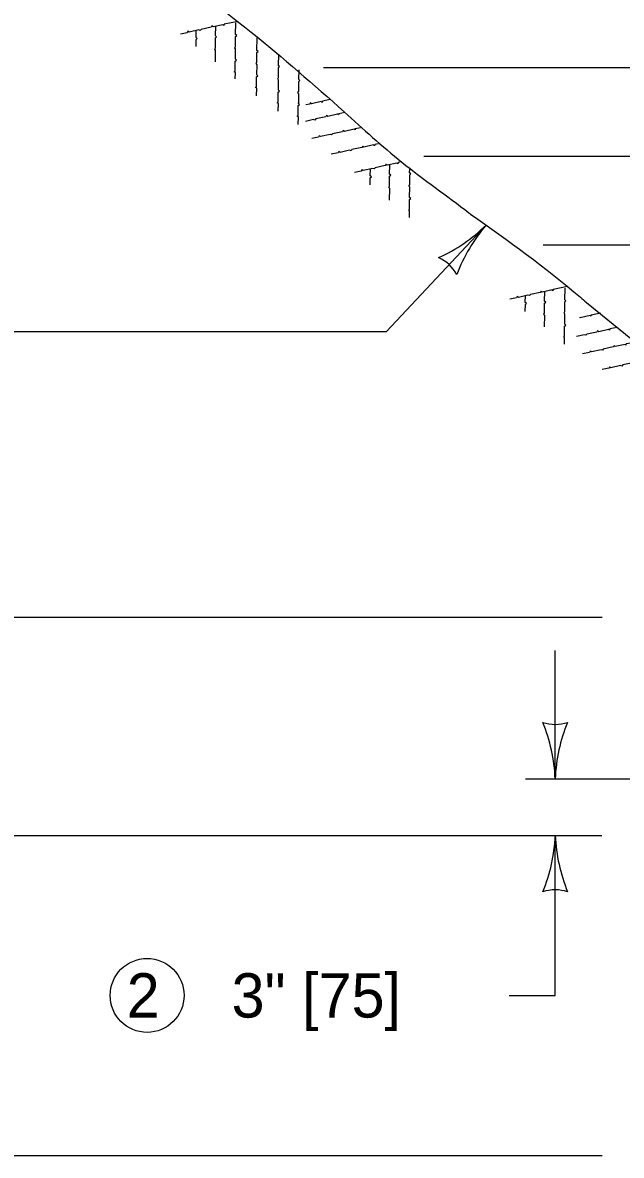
# Model space of a CAD drawing. Extents: x 49991.4 to 50021, y 49987.6 to 50011.4.
# Drawn here: x 50001.509 to 50002.319, y 49989.325 to 49990.858 of the extents above; entities that cross this region are included whole.
import ezdxf

# ---------------------------------------------------------------- set-up
doc = ezdxf.new("R2010")
doc.units = 0
for name, color, linetype in [('Level 1', 7, 'Continuous'), ('Level 2', 7, 'Continuous'), ('Level 3', 7, 'Continuous')]:
    doc.layers.add(name, color=color, linetype=linetype)

msp = doc.modelspace()

# ---------------------------------------------------------------- linework, layer by layer
at = {"layer": 'Level 1'}
for p, q in [((50001.9159, 49990.7972), (50003.1609, 49990.7972)), ((50002.0519, 49990.6772), (50003.0002, 49990.6772)), ((50002.2134, 49990.5572), (50002.9008, 49990.5572)), ((50002.2719, 49990.4789), (50002.3943, 49990.3794))]:
    msp.add_line(p, q, dxfattribs=at)
for points in [[(50001.8007, 49990.8593), (50001.7815, 49990.8556), (50001.781, 49990.8538), (50001.7798, 49990.8549), (50001.7666, 49990.8519), (50001.765, 49990.8532), (50001.7639, 49990.8515), (50001.7505, 49990.8486), (50001.7492, 49990.8471), (50001.7473, 49990.8478), (50001.7343, 49990.8448), (50001.7326, 49990.846), (50001.7316, 49990.8441), (50001.7225, 49990.8423)], [(50001.7697, 49990.8048), (50001.77, 49990.8204), (50001.7688, 49990.822), (50001.7698, 49990.8236), (50001.7698, 49990.8371), (50001.7713, 49990.8384), (50001.7697, 49990.8397), (50001.7702, 49990.8528)], [(50001.7965, 49990.7815), (50001.7969, 49990.7905), (50001.7953, 49990.7912), (50001.7966, 49990.7922), (50001.7967, 49990.8057), (50001.7984, 49990.807), (50001.797, 49990.8084), (50001.7972, 49990.8222), (50001.796, 49990.8238), (50001.7971, 49990.8255), (50001.7971, 49990.8388), (50001.7986, 49990.8402), (50001.7971, 49990.8415), (50001.7975, 49990.8573)], [(50001.7436, 49990.8255), (50001.7437, 49990.835), (50001.7452, 49990.8364), (50001.7436, 49990.8377), (50001.7439, 49990.8472)], [(50001.8254, 49990.7587), (50001.8257, 49990.769), (50001.8241, 49990.7698), (50001.8255, 49990.7708), (50001.8255, 49990.7842), (50001.8272, 49990.7856), (50001.8258, 49990.787), (50001.8261, 49990.8008), (50001.8249, 49990.8024), (50001.8259, 49990.804), (50001.826, 49990.8175), (50001.8275, 49990.8188), (50001.826, 49990.8202), (50001.8264, 49990.8374)], [(50001.8547, 49990.7381), (50001.855, 49990.7485), (50001.8534, 49990.7492), (50001.8547, 49990.7502), (50001.8548, 49990.7637), (50001.8565, 49990.765), (50001.8551, 49990.7664), (50001.8553, 49990.7801), (50001.8541, 49990.7818), (50001.8552, 49990.7835), (50001.8552, 49990.7968), (50001.8567, 49990.7982), (50001.8552, 49990.7995), (50001.8556, 49990.8149)], [(50001.8825, 49990.7487), (50001.8827, 49990.7615), (50001.8815, 49990.7631), (50001.8826, 49990.7648), (50001.8826, 49990.7781), (50001.8841, 49990.7795), (50001.8825, 49990.7809), (50001.883, 49990.7938)], [(50001.8818, 49990.7201), (50001.8822, 49990.7303), (50001.8805, 49990.7311), (50001.8817, 49990.732), (50001.8819, 49990.7455), (50001.8837, 49990.7468), (50001.8821, 49990.7483), (50001.8822, 49990.7491)], [(50001.8992, 49990.7486), (50001.8983, 49990.7493), (50001.8973, 49990.7476), (50001.8923, 49990.7464)], [(50001.925, 49990.7536), (50001.9147, 49990.7516), (50001.9144, 49990.7499), (50001.913, 49990.7509), (50001.8999, 49990.7479), (50001.8991, 49990.7487)], [(50001.9447, 49990.7361), (50001.9367, 49990.7345), (50001.9363, 49990.7328), (50001.9351, 49990.7338), (50001.9219, 49990.7308), (50001.9202, 49990.7323), (50001.9192, 49990.7304), (50001.9058, 49990.7277), (50001.9044, 49990.726), (50001.9026, 49990.7267), (50001.8918, 49990.7242)], [(50001.9662, 49990.7156), (50001.959, 49990.7142), (50001.9587, 49990.7125), (50001.9574, 49990.7135), (50001.9443, 49990.7106), (50001.9426, 49990.712), (50001.9416, 49990.7102), (50001.9281, 49990.7074), (50001.9268, 49990.7058), (50001.9249, 49990.7065), (50001.9118, 49990.7035), (50001.9102, 49990.7046), (50001.9092, 49990.7029), (50001.9001, 49990.701)], [(50001.9929, 49990.6943), (50001.9855, 49990.6929), (50001.9851, 49990.6911), (50001.9839, 49990.6922), (50001.9708, 49990.6893), (50001.9691, 49990.6906), (50001.968, 49990.6889), (50001.9545, 49990.686), (50001.9533, 49990.6845), (50001.9514, 49990.6851), (50001.9384, 49990.6821), (50001.9367, 49990.6833), (50001.9357, 49990.6814), (50001.9266, 49990.6796)], [(50002.0215, 49990.6693), (50002.0171, 49990.6684), (50002.0166, 49990.6666), (50002.0154, 49990.6677), (50002.0023, 49990.6648), (50002.0006, 49990.6661), (50001.9995, 49990.6644), (50001.986, 49990.6615), (50001.9848, 49990.66), (50001.9829, 49990.6606), (50001.9699, 49990.6576), (50001.9682, 49990.6589), (50001.9672, 49990.657), (50001.9581, 49990.6551)], [(50001.9793, 49990.6383), (50001.9793, 49990.6479), (50001.9808, 49990.6493), (50001.9793, 49990.6506), (50001.9795, 49990.6601)], [(50002.0053, 49990.6176), (50002.0056, 49990.6333), (50002.0044, 49990.6348), (50002.0054, 49990.6365), (50002.0055, 49990.65), (50002.007, 49990.6513), (50002.0054, 49990.6526), (50002.0058, 49990.665)], [(50002.0322, 49990.5943), (50002.0325, 49990.6033), (50002.031, 49990.6041), (50002.0322, 49990.605), (50002.0324, 49990.6186), (50002.0341, 49990.6199), (50002.0326, 49990.6213), (50002.0328, 49990.635), (50002.0316, 49990.6366), (50002.0327, 49990.6383), (50002.0327, 49990.6517), (50002.0342, 49990.6531), (50002.0326, 49990.6545), (50002.0328, 49990.6597)], [(50002.2461, 49990.5006), (50002.2269, 49990.4969), (50002.2264, 49990.4951), (50002.2252, 49990.4962), (50002.212, 49990.4932), (50002.2104, 49990.4945), (50002.2093, 49990.4928), (50002.1959, 49990.4899), (50002.1946, 49990.4884), (50002.1926, 49990.4891), (50002.1797, 49990.4861), (50002.178, 49990.4873), (50002.177, 49990.4854), (50002.1679, 49990.4836)], [(50002.2419, 49990.4228), (50002.2423, 49990.4318), (50002.2407, 49990.4325), (50002.242, 49990.4335), (50002.2421, 49990.447), (50002.2438, 49990.4483), (50002.2424, 49990.4497), (50002.2426, 49990.4635), (50002.2414, 49990.4651), (50002.2425, 49990.4668), (50002.2425, 49990.4801), (50002.244, 49990.4815), (50002.2425, 49990.4828), (50002.2429, 49990.4986)], [(50002.189, 49990.4668), (50002.1891, 49990.4763), (50002.1906, 49990.4777), (50002.189, 49990.479), (50002.1893, 49990.4885)], [(50002.2151, 49990.4461), (50002.2154, 49990.4617), (50002.2142, 49990.4633), (50002.2152, 49990.4649), (50002.2152, 49990.4784), (50002.2167, 49990.4797), (50002.2151, 49990.4811), (50002.2156, 49990.4941)], [(50002.2906, 49990.4647), (50002.2782, 49990.4622), (50002.2779, 49990.4605), (50002.2766, 49990.4615), (50002.2634, 49990.4585), (50002.2626, 49990.4593)], [(50002.3133, 49990.4452), (50002.3033, 49990.4433), (50002.3029, 49990.4415), (50002.3016, 49990.4425), (50002.2884, 49990.4396), (50002.2869, 49990.441), (50002.2857, 49990.4392), (50002.2723, 49990.4364), (50002.271, 49990.4348), (50002.2691, 49990.4355), (50002.2583, 49990.433)], [(50002.3379, 49990.4252), (50002.3256, 49990.423), (50002.3252, 49990.4212), (50002.324, 49990.4222), (50002.3108, 49990.4194), (50002.3091, 49990.4207), (50002.3081, 49990.419), (50002.2946, 49990.4162), (50002.2933, 49990.4145), (50002.2915, 49990.4152), (50002.2784, 49990.4122), (50002.2767, 49990.4134), (50002.2758, 49990.4116), (50002.2666, 49990.4098)], [(50002.3639, 49990.404), (50002.3521, 49990.4016), (50002.3517, 49990.3999), (50002.3505, 49990.4009), (50002.3373, 49990.398), (50002.3356, 49990.3993), (50002.3346, 49990.3976), (50002.3211, 49990.3948), (50002.3198, 49990.3932), (50002.3179, 49990.3938), (50002.3049, 49990.3909), (50002.3033, 49990.3919), (50002.3022, 49990.3902), (50002.2931, 49990.3884)]]:
    msp.add_lwpolyline(points, dxfattribs=at)
for points in [[(50001.6697, 49990.9573), (50001.8181, 49990.8449), (50001.944, 49990.737), (50002.0219, 49990.669), (50002.1128, 49990.6004), (50002.1151, 49990.5986)], [(50002.1151, 49990.5986), (50002.2635, 49990.4862), (50002.2719, 49990.4789)]]:
    msp.add_spline(points, degree=3, dxfattribs=at)
at = {"layer": 'Level 2'}
msp.add_circle((50001.6774, 49989.5417), 0.05, dxfattribs=at)
at = {"layer": 'Level 3'}
for p, q in [((50002.1361, 49990.5839), (50002.0012, 49990.44)), ((50001.0483, 49990.44), (50002.0012, 49990.44)), ((50001.4254, 49990.0533), (50002.2929, 49990.0533)), ((50002.2295, 49989.8349), (50002.2295, 49990.0083)), ((50002.1895, 49989.8349), (50003.255, 49989.8349)), ((50001.4254, 49989.7579), (50002.2924, 49989.7579)), ((50002.2295, 49989.5417), (50002.2295, 49989.7579)), ((50002.167, 49989.5417), (50002.2295, 49989.5417)), ((50001.4254, 49989.3253), (50002.2929, 49989.3253))]:
    msp.add_line(p, q, dxfattribs=at)
for centre, radius, start, end in [((50001.9803, 49990.7425), 0.2223, 294.3067, 314.4902), ((50002.3137, 49990.4332), 0.233, 139.678, 158.9279), ((50002.0484, 49990.4904), 0.0548, 28.9895, 64.7119), ((50002.2295, 49989.9631), 0.0548, 252.1388, 287.8612), ((50001.9968, 49989.8234), 0.233, 2.8273, 22.0772), ((50002.4516, 49989.8258), 0.2223, 157.456, 177.6395), ((50002.0074, 49989.767), 0.2223, 337.456, 357.6395), ((50002.4622, 49989.7694), 0.233, 182.8273, 202.0772), ((50002.2295, 49989.6297), 0.0548, 72.1388, 107.8612)]:
    msp.add_arc(centre, radius, start, end, dxfattribs=at)

# ---------------------------------------------------------------- texts
at = {"layer": 'Level 2'}
for s, p in [('2', (50001.6498, 49989.5117)), ('3" [75]', (50001.7917, 49989.5117))]:
    msp.add_text(s, height=0.06, dxfattribs=at).set_placement(p)

doc.saveas('drawing.dxf')
